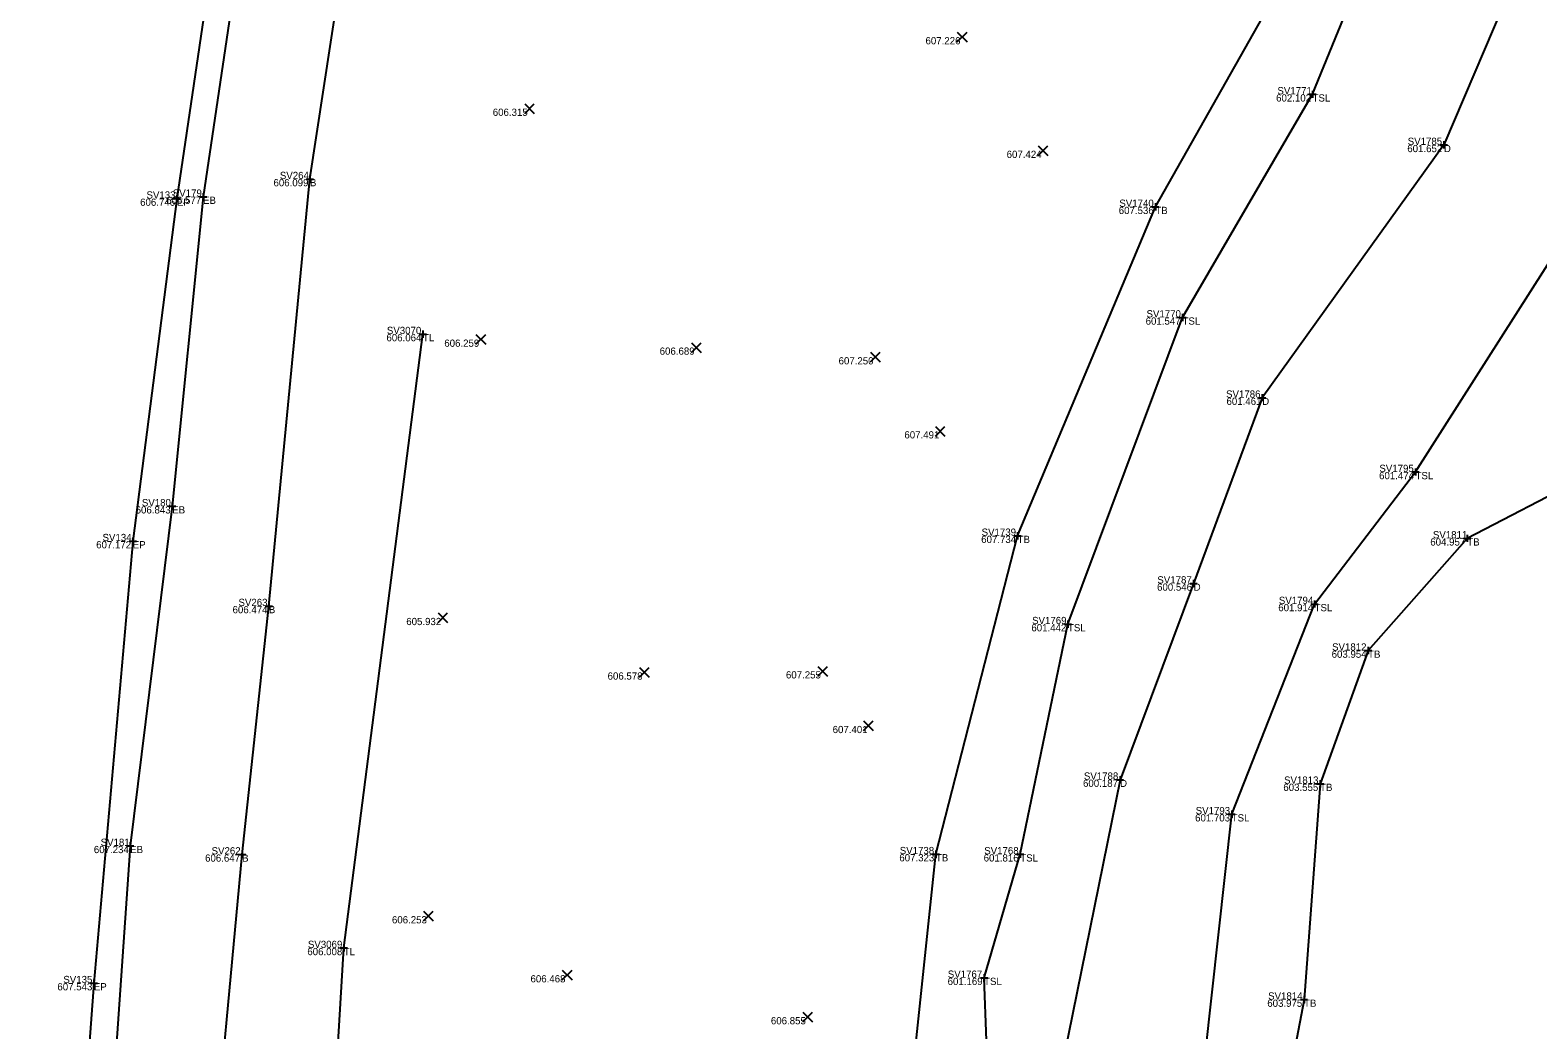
# Model space of a CAD drawing. Extents: x -2 to 1979875, y -2 to 232027.
# Drawn here: x 1978795.3 to 1978899.5, y 231462.4 to 231531.5 of the extents above; entities that cross this region are included whole.
import ezdxf

# ---------------------------------------------------------------- set-up
doc = ezdxf.new("R2010")
doc.units = 0
for name, color, linetype in [('_CIVIL_CONSTRUCTION', 7, 'Continuous'), ('DR_X_Ditch', 7, 'Continuous'), ('GE_P_Alignment', 7, 'Continuous'), ('GE_P_Alignment_1000_Curve_Data', 7, 'Continuous'), ('GE_X_Alignment', 7, 'Continuous'), ('GE_X_Alignment_1000_Stations', 7, 'Continuous'), ('GE_X_Alignment_100_Curve_Data', 7, 'Continuous'), ('GE_X_Alignment_100_Stations', 7, 'Continuous'), ('HY_X_Water_Edge', 7, 'Continuous'), ('SC_Scratch1', 7, 'Continuous'), ('SV_X_Random_Point', 7, 'Continuous'), ('SV_X_Toe_of_Slope', 7, 'Continuous'), ('SV_X_Top_of_Bank', 7, 'Continuous')]:
    doc.layers.add(name, color=color, linetype=linetype)

msp = doc.modelspace()

# ---------------------------------------------------------------- linework, layer by layer
at = {"layer": 'DR_X_Ditch'}
msp.add_lwpolyline([(1978962.19, 231606.29), (1978949.61, 231595.73), (1978937.1, 231586.52), (1978924.62, 231577.27), (1978916.58, 231558.51), (1978902.78, 231546.53), (1978893.02, 231523.59), (1978880.46, 231506.11), (1978875.72, 231493.26), (1978870.63, 231479.69), (1978866.76, 231460.62), (1978868.55, 231441.92)], dxfattribs=at)
at = {"layer": 'GE_P_Alignment'}
msp.add_lwpolyline([(1978796.54, 231298.86), (1978798.27, 231324.44), (1978800.7, 231350.05), (1978802.69, 231376.87), (1978804.91, 231401.65), (1978806.89, 231425.4), (1978807.69, 231450.45), (1978809.93, 231474.52), (1978811.78, 231491.7), (1978814.62, 231521.23), (1978818.44, 231546.21), (1978822.85, 231572.07), (1978827.06, 231594.68), (1978834.58, 231618.81), (1978841.49, 231643.19), (1978848.45, 231666.52), (1978859.66, 231691.19), (1978869.57, 231712.59), (1978880.4, 231735.41), (1978890.4, 231756.48), (1978895.24, 231765.92)], dxfattribs=at)
at = {"layer": 'GE_P_Alignment_1000_Curve_Data'}
msp.add_lwpolyline([(1978800.25, 231250.2), (1978805.28, 231291.39), (1978804.51, 231297.59), (1978804.78, 231306.07), (1978804.46, 231312.37), (1978805.15, 231324.32), (1978805.16, 231336.37), (1978807.19, 231350.11), (1978807.85, 231360.67), (1978809.09, 231373.35), (1978811.12, 231382.98), (1978814.16, 231421.1), (1978816.96, 231468.05), (1978822.43, 231510.51)], dxfattribs=at)
at = {"layer": 'GE_X_Alignment_1000_Stations'}
msp.add_lwpolyline([(1978887.05, 231769.5), (1978875.69, 231747.11), (1978865.32, 231725.63), (1978856.26, 231705.08), (1978847.49, 231684.38), (1978839.46, 231663.38), (1978831.79, 231640.15), (1978824.65, 231616.12), (1978817.77, 231591.52), (1978812.87, 231567.29), (1978809.01, 231544.23), (1978805.42, 231519.88), (1978802.37, 231496.19), (1978799.68, 231465.62), (1978797.96, 231442.35), (1978795.89, 231416.69), (1978793.94, 231391.43), (1978792.63, 231370.42), (1978791.34, 231345.81), (1978789.97, 231322.68), (1978787.96, 231301.58), (1978787.71, 231292.48)], dxfattribs=at)
at = {"layer": 'GE_X_Alignment_100_Curve_Data'}
for p, q in [((1978883.69, 231527.09), (1978884.19, 231527.09)), ((1978883.94, 231527.34), (1978883.94, 231526.84)), ((1978883.94, 231527.09), (1978883.94, 231527.09)), ((1978892.77, 231523.59), (1978893.27, 231523.59)), ((1978893.02, 231523.84), (1978893.02, 231523.34)), ((1978893.02, 231523.59), (1978893.02, 231523.59)), ((1978814.62, 231521.48), (1978814.62, 231520.98)), ((1978814.37, 231521.23), (1978814.87, 231521.23)), ((1978814.62, 231521.23), (1978814.62, 231521.23)), ((1978805.17, 231519.88), (1978805.67, 231519.88)), ((1978805.42, 231520.13), (1978805.42, 231519.63)), ((1978805.42, 231519.88), (1978805.42, 231519.88)), ((1978806.98, 231520.01), (1978807.48, 231520.01)), ((1978807.23, 231520.26), (1978807.23, 231519.76)), ((1978807.23, 231520.01), (1978807.23, 231520.01)), ((1978873.07, 231519.56), (1978873.07, 231519.06)), ((1978872.82, 231519.31), (1978873.32, 231519.31)), ((1978873.07, 231519.31), (1978873.07, 231519.31)), ((1978874.7, 231511.66), (1978875.2, 231511.66)), ((1978874.95, 231511.91), (1978874.95, 231511.41)), ((1978874.95, 231511.66), (1978874.95, 231511.66)), ((1978822.18, 231510.51), (1978822.68, 231510.51)), ((1978822.43, 231510.76), (1978822.43, 231510.26)), ((1978822.43, 231510.51), (1978822.43, 231510.51)), ((1978880.21, 231506.11), (1978880.71, 231506.11)), ((1978880.46, 231506.36), (1978880.46, 231505.86)), ((1978880.46, 231506.11), (1978880.46, 231506.11)), ((1978890.81, 231500.97), (1978891.31, 231500.97)), ((1978891.06, 231501.22), (1978891.06, 231500.72)), ((1978891.06, 231500.97), (1978891.06, 231500.97)), ((1978804.85, 231498.6), (1978805.35, 231498.6)), ((1978805.1, 231498.85), (1978805.1, 231498.35)), ((1978805.1, 231498.6), (1978805.1, 231498.6)), ((1978802.37, 231496.44), (1978802.37, 231495.94)), ((1978863.3, 231496.56), (1978863.8, 231496.56)), ((1978863.55, 231496.81), (1978863.55, 231496.31)), ((1978863.55, 231496.56), (1978863.55, 231496.56)), ((1978894.64, 231496.63), (1978894.64, 231496.13)), ((1978802.12, 231496.19), (1978802.62, 231496.19)), ((1978802.37, 231496.19), (1978802.37, 231496.19)), ((1978894.39, 231496.38), (1978894.89, 231496.38)), ((1978894.64, 231496.38), (1978894.64, 231496.38)), ((1978875.72, 231493.51), (1978875.72, 231493.01)), ((1978875.47, 231493.26), (1978875.97, 231493.26)), ((1978875.72, 231493.26), (1978875.72, 231493.26)), ((1978811.53, 231491.7), (1978812.03, 231491.7)), ((1978811.78, 231491.95), (1978811.78, 231491.45)), ((1978811.78, 231491.7), (1978811.78, 231491.7)), ((1978883.83, 231491.84), (1978884.33, 231491.84)), ((1978884.08, 231492.09), (1978884.08, 231491.59)), ((1978884.08, 231491.84), (1978884.08, 231491.84)), ((1978866.78, 231490.45), (1978867.28, 231490.45)), ((1978867.03, 231490.7), (1978867.03, 231490.2)), ((1978867.03, 231490.45), (1978867.03, 231490.45)), ((1978887.53, 231488.62), (1978888.03, 231488.62)), ((1978887.78, 231488.87), (1978887.78, 231488.37)), ((1978887.78, 231488.62), (1978887.78, 231488.62)), ((1978870.63, 231479.94), (1978870.63, 231479.44)), ((1978870.38, 231479.69), (1978870.88, 231479.69)), ((1978870.63, 231479.69), (1978870.63, 231479.69)), ((1978884.21, 231479.41), (1978884.71, 231479.41)), ((1978884.46, 231479.66), (1978884.46, 231479.16)), ((1978884.46, 231479.41), (1978884.46, 231479.41)), ((1978878.1, 231477.3), (1978878.6, 231477.3)), ((1978878.35, 231477.55), (1978878.35, 231477.05)), ((1978878.35, 231477.3), (1978878.35, 231477.3)), ((1978801.94, 231475.11), (1978802.44, 231475.11)), ((1978802.19, 231475.36), (1978802.19, 231474.86)), ((1978802.19, 231475.11), (1978802.19, 231475.11)), ((1978809.68, 231474.52), (1978810.18, 231474.52)), ((1978809.93, 231474.77), (1978809.93, 231474.27)), ((1978809.93, 231474.52), (1978809.93, 231474.52)), ((1978857.65, 231474.54), (1978858.15, 231474.54)), ((1978857.9, 231474.79), (1978857.9, 231474.29)), ((1978857.9, 231474.54), (1978857.9, 231474.54)), ((1978863.48, 231474.53), (1978863.98, 231474.53)), ((1978863.73, 231474.78), (1978863.73, 231474.28)), ((1978863.73, 231474.53), (1978863.73, 231474.53)), ((1978816.96, 231468.3), (1978816.96, 231467.8)), ((1978816.71, 231468.05), (1978817.21, 231468.05)), ((1978816.96, 231468.05), (1978816.96, 231468.05)), ((1978861.23, 231466.24), (1978861.23, 231465.74)), ((1978799.43, 231465.62), (1978799.93, 231465.62)), ((1978799.68, 231465.88), (1978799.68, 231465.38)), ((1978799.68, 231465.62), (1978799.68, 231465.62)), ((1978860.98, 231465.99), (1978861.48, 231465.99)), ((1978861.23, 231465.99), (1978861.23, 231465.99)), ((1978883.1, 231464.48), (1978883.6, 231464.48)), ((1978883.35, 231464.73), (1978883.35, 231464.23)), ((1978883.35, 231464.48), (1978883.35, 231464.48))]:
    msp.add_line(p, q, dxfattribs=at)
at = {"layer": 'HY_X_Water_Edge'}
for points in [[(1978862.05, 231444.32), (1978861.23, 231465.99), (1978863.73, 231474.53), (1978867.03, 231490.45), (1978874.95, 231511.66), (1978883.94, 231527.09), (1978886.49, 231533.36), (1978891.21, 231540.88), (1978905.93, 231559.12)], [(1978903.08, 231327.23), (1978894.36, 231372.19), (1978894.66, 231399.85), (1978884.96, 231411.07), (1978878.07, 231425.73), (1978877.43, 231441.5), (1978876.51, 231460.62), (1978878.35, 231477.3), (1978884.08, 231491.84), (1978891.06, 231500.97), (1978902.06, 231518.22)]]:
    msp.add_lwpolyline(points, dxfattribs=at)
at = {"layer": 'SC_Scratch1'}
msp.add_lwpolyline([(1978888.81, 231768.48), (1978877.88, 231747.21), (1978866.82, 231724.39), (1978857.22, 231702.34), (1978848.24, 231681.51), (1978839.53, 231658.2), (1978831.77, 231633.74), (1978825.1, 231611.48), (1978819.56, 231589.92), (1978815.24, 231567.91), (1978810.74, 231543.66), (1978807.23, 231520.01), (1978805.1, 231498.6), (1978802.19, 231475.11), (1978800.52, 231451.18), (1978799.2, 231426.9), (1978797.07, 231402.16), (1978795.91, 231377.32), (1978794.64, 231352.24), (1978792.96, 231328.96), (1978791.06, 231305.23), (1978790.04, 231294.4)], dxfattribs=at)
at = {"layer": 'SV_X_Random_Point'}
for p, q in [((1978859.38, 231530.71), (1978860.05, 231531.38)), ((1978859.38, 231531.38), (1978860.05, 231530.71)), ((1978829.47, 231525.77), (1978830.13, 231526.43)), ((1978829.47, 231526.43), (1978830.13, 231525.77)), ((1978864.97, 231522.86), (1978865.64, 231523.53)), ((1978864.97, 231523.53), (1978865.64, 231522.86)), ((1978826.1, 231509.8), (1978826.77, 231510.47)), ((1978826.1, 231510.47), (1978826.77, 231509.8)), ((1978840.99, 231509.24), (1978841.66, 231509.91)), ((1978840.99, 231509.91), (1978841.66, 231509.24)), ((1978853.37, 231508.58), (1978854.04, 231509.25)), ((1978853.37, 231509.25), (1978854.04, 231508.58)), ((1978857.86, 231503.45), (1978858.52, 231504.12)), ((1978857.86, 231504.12), (1978858.52, 231503.45)), ((1978823.48, 231490.55), (1978824.14, 231491.22)), ((1978823.48, 231491.22), (1978824.14, 231490.55)), ((1978837.4, 231486.78), (1978838.07, 231487.45)), ((1978837.4, 231487.45), (1978838.07, 231486.78)), ((1978849.73, 231486.85), (1978850.4, 231487.52)), ((1978849.73, 231487.52), (1978850.4, 231486.85)), ((1978852.89, 231483.08), (1978853.56, 231483.75)), ((1978852.89, 231483.75), (1978853.56, 231483.08)), ((1978822.48, 231469.92), (1978823.14, 231470.59)), ((1978822.48, 231470.59), (1978823.14, 231469.92)), ((1978832.07, 231465.84), (1978832.74, 231466.51)), ((1978832.07, 231466.51), (1978832.74, 231465.84)), ((1978848.7, 231462.94), (1978849.36, 231463.61)), ((1978848.7, 231463.61), (1978849.36, 231462.94))]:
    msp.add_line(p, q, dxfattribs=at)
at = {"layer": 'SV_X_Toe_of_Slope'}
for points in [[(1978862.05, 231444.32), (1978861.23, 231465.99), (1978863.73, 231474.53), (1978867.03, 231490.45), (1978874.95, 231511.66), (1978883.94, 231527.09), (1978886.49, 231533.36), (1978891.21, 231540.88), (1978905.93, 231559.12), (1978916.42, 231576.44), (1978923.02, 231585.21), (1978936.55, 231594.94), (1978953.84, 231610.59)], [(1978877.43, 231441.5), (1978876.51, 231460.62), (1978878.35, 231477.3), (1978884.08, 231491.84), (1978891.06, 231500.97), (1978902.06, 231518.22), (1978905.68, 231527.62), (1978917.18, 231541.58), (1978923.8, 231554.16), (1978935.08, 231565.85), (1978947.42, 231581.38), (1978957.98, 231589.89), (1978970.17, 231597.91)]]:
    msp.add_lwpolyline(points, dxfattribs=at)
at = {"layer": 'SV_X_Top_of_Bank'}
for points in [[(1978855.76, 231442.43), (1978856.06, 231457.01), (1978857.9, 231474.54), (1978863.55, 231496.56), (1978873.07, 231519.31), (1978884.15, 231538.9), (1978898.65, 231557.24), (1978909.07, 231573.13), (1978911.03, 231578.63), (1978909.61, 231583.71), (1978914.7, 231591.39), (1978921.84, 231593.62), (1978928.84, 231591.83), (1978939.39, 231606.19)], [(1978970.43, 231596.93), (1978955.71, 231583.37), (1978942.85, 231568.03), (1978930.15, 231553.86), (1978923.45, 231536.94), (1978913.26, 231522.92), (1978902.63, 231500.51), (1978894.64, 231496.38), (1978887.78, 231488.62), (1978884.46, 231479.41), (1978883.35, 231464.48), (1978880.85, 231451.36), (1978883.99, 231440.74)]]:
    msp.add_lwpolyline(points, dxfattribs=at)

# ---------------------------------------------------------------- texts
at = {"layer": '_CIVIL_CONSTRUCTION'}
for s, p in [('607.226', (1978857.18, 231530.55)), ('602.102', (1978881.42, 231526.59)), ('606.315', (1978827.26, 231525.6)), ('601.652', (1978890.49, 231523.09)), ('607.424', (1978862.79, 231522.69)), ('606.099', (1978812.1, 231520.73)), ('606.746', (1978802.88, 231519.38)), ('606.577', (1978804.68, 231519.51)), ('607.536', (1978870.54, 231518.81)), ('601.547', (1978872.4, 231511.16)), ('606.064', (1978819.91, 231510.01)), ('606.259', (1978823.91, 231509.63)), ('606.689', (1978838.8, 231509.08)), ('607.250', (1978851.17, 231508.41)), ('601.461', (1978877.99, 231505.61)), ('607.491', (1978855.72, 231503.29)), ('601.474', (1978888.54, 231500.47)), ('606.843', (1978802.57, 231498.1)), ('607.734', (1978861.03, 231496.06)), ('607.172', (1978799.84, 231495.69)), ('604.957', (1978892.08, 231495.88)), ('600.546', (1978873.19, 231492.76)), ('606.474', (1978809.27, 231491.2)), ('601.914', (1978881.57, 231491.34)), ('605.932', (1978821.28, 231490.38)), ('601.442', (1978864.5, 231489.95)), ('603.954', (1978885.26, 231488.12)), ('606.578', (1978835.2, 231486.61)), ('607.255', (1978847.53, 231486.69)), ('607.401', (1978850.76, 231482.91)), ('600.187', (1978868.07, 231479.19)), ('603.555', (1978881.92, 231478.91)), ('601.703', (1978875.82, 231476.8)), ('607.234', (1978799.68, 231474.61)), ('606.647', (1978807.37, 231474.02)), ('607.323', (1978855.37, 231474.04)), ('601.816', (1978861.2, 231474.03)), ('606.253', (1978820.29, 231469.75)), ('606.008', (1978814.44, 231467.55)), ('606.468', (1978829.87, 231465.67)), ('607.543', (1978797.16, 231465.12)), ('601.169', (1978858.71, 231465.49)), ('603.975', (1978880.81, 231463.98)), ('606.855', (1978846.49, 231462.77))]:
    msp.add_text(s, height=0.5, dxfattribs=at).set_placement(p)
at = {"layer": 'GE_X_Alignment'}
for s, p in [('SV1771', (1978881.51, 231527.09)), ('SV1785', (1978890.52, 231523.59)), ('SV264', (1978812.54, 231521.23)), ('SV133', (1978803.32, 231519.88)), ('SV179', (1978805.14, 231520.01)), ('SV1740', (1978870.58, 231519.31)), ('SV1770', (1978872.46, 231511.66)), ('SV3070', (1978819.94, 231510.51)), ('SV1786', (1978877.96, 231506.11)), ('SV1795', (1978888.56, 231500.97)), ('SV180', (1978803, 231498.6)), ('SV134', (1978800.28, 231496.19)), ('SV1739', (1978861.06, 231496.56)), ('SV1811', (1978892.26, 231496.38)), ('SV1787', (1978873.21, 231493.26)), ('SV1794', (1978881.61, 231491.84)), ('SV263', (1978809.68, 231491.7)), ('SV1769', (1978864.55, 231490.45)), ('SV1812', (1978885.29, 231488.62)), ('SV1788', (1978868.13, 231479.69)), ('SV1813', (1978881.97, 231479.41)), ('SV1793', (1978875.86, 231477.3)), ('SV181', (1978800.15, 231475.11)), ('SV262', (1978807.82, 231474.52)), ('SV1738', (1978855.4, 231474.54)), ('SV1768', (1978861.24, 231474.53)), ('SV3069', (1978814.48, 231468.05)), ('SV1767', (1978858.72, 231465.99)), ('SV135', (1978797.57, 231465.62)), ('SV1814', (1978880.87, 231464.48))]:
    msp.add_text(s, height=0.5, dxfattribs=at).set_placement(p)
at = {"layer": 'GE_X_Alignment_100_Stations'}
for s, p in [('TSL', (1978883.94, 231526.59)), ('D', (1978893.02, 231523.09)), ('B', (1978814.62, 231520.73)), ('EP', (1978805.42, 231519.38)), ('EB', (1978807.23, 231519.51)), ('TB', (1978873.07, 231518.81)), ('TSL', (1978874.95, 231511.16)), ('TL', (1978822.43, 231510.01)), ('D', (1978880.46, 231505.61)), ('TSL', (1978891.06, 231500.47)), ('EB', (1978805.1, 231498.1)), ('TB', (1978863.55, 231496.06)), ('EP', (1978802.37, 231495.69)), ('TB', (1978894.64, 231495.88)), ('D', (1978875.72, 231492.76)), ('B', (1978811.78, 231491.2)), ('TSL', (1978884.08, 231491.34)), ('TSL', (1978867.03, 231489.95)), ('TB', (1978887.78, 231488.12)), ('D', (1978870.63, 231479.19)), ('TB', (1978884.46, 231478.91)), ('TSL', (1978878.35, 231476.8)), ('EB', (1978802.19, 231474.61)), ('B', (1978809.93, 231474.02)), ('TB', (1978857.9, 231474.04)), ('TSL', (1978863.73, 231474.03)), ('TL', (1978816.96, 231467.55)), ('EP', (1978799.68, 231465.12)), ('TSL', (1978861.23, 231465.49)), ('TB', (1978883.35, 231463.98))]:
    msp.add_text(s, height=0.5, dxfattribs=at).set_placement(p)

doc.saveas('drawing.dxf')
